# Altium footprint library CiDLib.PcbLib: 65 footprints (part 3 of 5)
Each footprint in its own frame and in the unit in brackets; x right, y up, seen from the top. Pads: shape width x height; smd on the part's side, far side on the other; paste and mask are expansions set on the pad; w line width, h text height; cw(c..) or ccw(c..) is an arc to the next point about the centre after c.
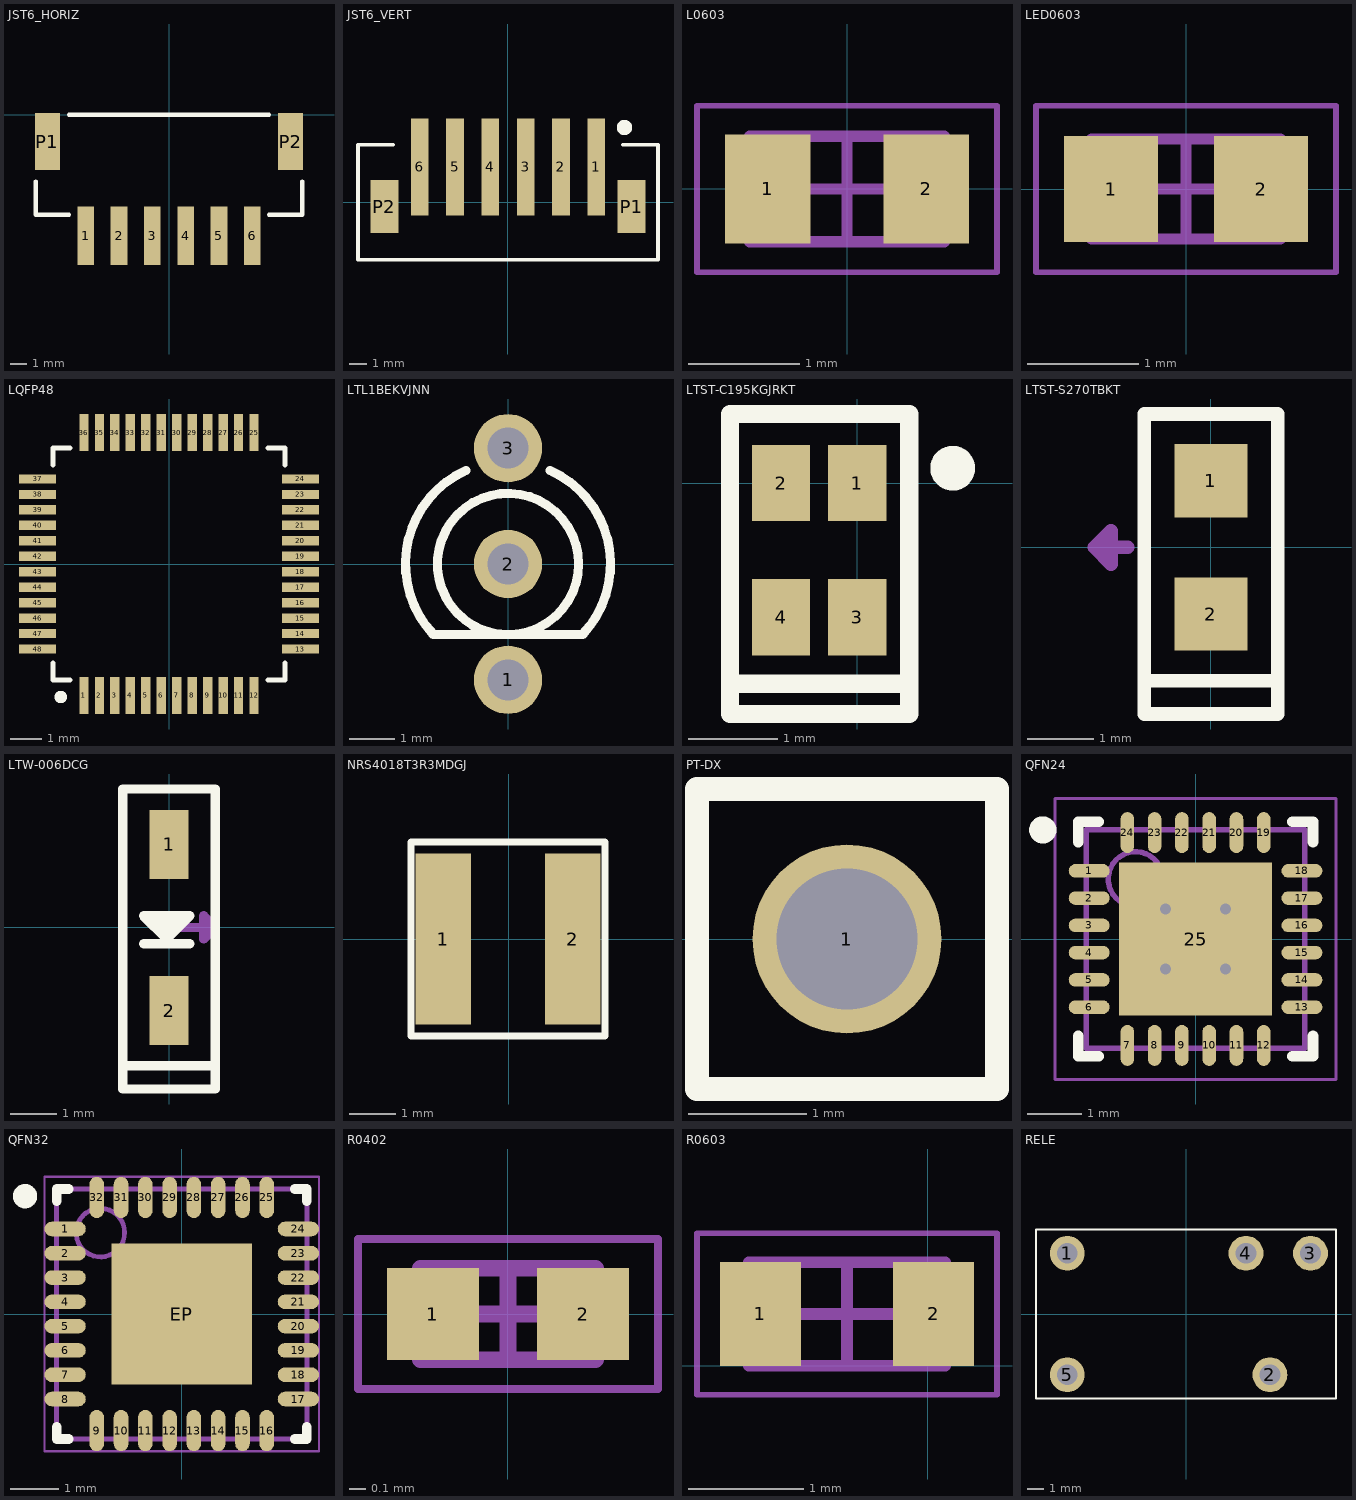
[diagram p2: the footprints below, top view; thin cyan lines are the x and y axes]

## JST6_HORIZ [mm] "SMT Horizontal JST 6 leads connector"
pads (8):
  rect 1x3.5 smd: 1(-5,-7.25) 2(-3,-7.25) 3(-1,-7.25) 4(1,-7.25) 5(3,-7.25) 6(5,-7.25)
  rect 1.5x3.4 smd: P1(-7.3,-1.6) P2(7.3,-1.6)
Top Overlay:
  lines w0.254: -8,-4 -8,-6 -6,-6 ; -6,0 6,0 ; 6,-6 8,-6 8,-4
3D body "S6B-PH-SM4-TB.STEP": height 5.5, standoff -0.1, extent -7.95,-8.6 7.95,0

## JST6_VERT [mm]
pads (8):
  rect 1x5.5 smd: 1(5,2) 2(3,2) 3(1,2) 4(-1,2) 5(-3,2) 6(-5,2)
  rect 1.6x3 smd: P1(7,-0.25) P2(-7,-0.25)
Top Overlay:
  circle w0.508: c6.605,4.235 r0.18
  lines w0.203: -6.5,3.25 -8.5,3.25 -8.5,-3.25 8.5,-3.25 8.5,3.25 6.5,3.25
3D body "A2001WV-S-6P.STEP": height 6.01, standoff 0.01, extent -8,-2.75 8,4.75

## L0603 [mm]
height 0.8
pads (2):
  rect 0.77x0.98 smd: 1(-0.715,0) 2(0.715,0)
Mechanical 13:
  lines w0.1: -0.875,-0.475 -0.875,0.475 0.875,0.475 0.875,-0.475 -0.875,-0.475
Mechanical 15:
  lines w0.05: -1.35,-0.75 -1.35,0.75 1.35,0.75 1.35,-0.75 -1.35,-0.75
  lines w0.1: -0.475,0 0.475,0 ; 0,-0.475 0,0.475
3D body: height 0.8, standoff 0, extent -0.575,-0.475 0.575,0.475
3D body: height 0.8, standoff 0, extent -0.875,-0.475 -0.575,0.475
3D body: height 0.8, standoff 0, extent 0.575,-0.475 0.875,0.475

## LED0603 [mm]
height 0.4
pads (2):
  rect 0.85x0.95 smd: 1(-0.675,0) 2(0.675,0)
Mechanical 13:
  lines w0.1: -0.85,-0.45 -0.85,0.45 0.85,0.45 0.85,-0.45 -0.85,-0.45
Mechanical 15:
  lines w0.05: -1.35,-0.75 -1.35,0.75 1.35,0.75 1.35,-0.75 -1.35,-0.75
  lines w0.1: -0.45,0 0.45,0 ; 0,-0.45 0,0.45
3D body: height 0.4, standoff 0, extent -0.45,-0.45 0.45,0.45
3D body: height 0.4, standoff 0, extent -0.85,-0.45 -0.45,0.45
3D body: height 0.4, standoff 0, extent 0.45,-0.45 0.85,0.45

## LQFP48 [mm]
pads (48):
  rect 0.3x1.2 smd mask+0.051: 1(-2.75,-4.25) 2(-2.25,-4.25) 3(-1.75,-4.25) 4(-1.25,-4.25) 5(-0.75,-4.25) 6(-0.25,-4.25) 7(0.25,-4.25) 8(0.75,-4.25) 9(1.25,-4.25) 10(1.75,-4.25) 11(2.25,-4.25) 12(2.75,-4.25) 25(2.75,4.25) 26(2.25,4.25) 27(1.75,4.25) 28(1.25,4.25) 29(0.75,4.25) 30(0.25,4.25) 31(-0.25,4.25) 32(-0.75,4.25) 33(-1.25,4.25) 34(-1.75,4.25) 35(-2.25,4.25) 36(-2.75,4.25)
  rect 1.2x0.3 smd mask+0.051: 13(4.25,-2.75) 14(4.25,-2.25) 15(4.25,-1.75) 16(4.25,-1.25) 17(4.25,-0.75) 18(4.25,-0.25) 19(4.25,0.25) 20(4.25,0.75) 21(4.25,1.25) 22(4.25,1.75) 23(4.25,2.25) 24(4.25,2.75) 37(-4.25,2.75) 38(-4.25,2.25) 39(-4.25,1.75) 40(-4.25,1.25) 41(-4.25,0.75) 42(-4.25,0.25) 43(-4.25,-0.25) 44(-4.25,-0.75) 45(-4.25,-1.25) 46(-4.25,-1.75) 47(-4.25,-2.25) 48(-4.25,-2.75)
Top Overlay:
  circle w0.203: c-3.5,-4.3 r0.1
  lines w0.152: -3.75,-3.2 -3.75,-3.75 -3.2,-3.75 ; -3.75,3.2 -3.75,3.75 -3.2,3.75 ; 3.2,-3.75 3.75,-3.75 3.75,-3.2 ; 3.2,3.75 3.75,3.75 3.75,3.2
3D body: height 1.6, standoff 0, extent -3.5,-3.5 3.5,3.5

## LTL1BEKVJNN [mm] "LED GRN/RED DIFF 3MM ROUND T/H"
height 5.15
pads (3):
  round 1.5 hole 0.9: 1(0,-2.54) 2(0,0) 3(0,2.54)
Top Overlay:
  circle w0.2: c0,0 r1.55
  lines w0.2: -1.64,-1.55 1.64,-1.55 ; -1.64,-1.541 cw(c0,0) -0.923,2.052 ; 0.923,2.052 cw(c0,0) 1.64,-1.541
3D body "User Library-3mmBiColorLED.step": height 7.51, standoff -2.53, extent -2.024,-2.794 2.024,2.794

## LTST-C195KGJRKT [mm] "Green-Red 571nm 631nm 2V-2V  0606"
pads (4):
  rect 0.65x0.85 smd: 1(0,0) 2(-0.85,0) 3(0,-1.499) 4(-0.85,-1.499)
Top Overlay:
  circle w0.25: c1.067,0.166 r0.125
  lines w0.203: -1.419,-2.579 0.581,-2.579 ; -1.419,-2.579 -1.419,-2.242 0.581,-2.242 0.581,-2.579 ; -1.419,-2.579 -1.419,0.772 0.581,0.772 0.581,-2.579

## LTST-S270TBKT [mm]
pads (2):
  rect 1.1x1.1 smd: 1(0,1) 2(0,-1)
Top Overlay:
  lines w0.203: -1,-2 1,-2 ; -1,-2 -1,2 1,2 1,-2 ; -1,-2 -1,-2.5 1,-2.5 1,-2
Mechanical 13:
  lines w0.203: -1.25,0 -1.75,0 ; -1.75,0 -1.5,-0.25 -1.5,0.25 -1.75,0
3D body: height 0.6, standoff 0, extent -0.81,-0.825 0.34,0.825

## LTW-006DCG [mm]
pads (2):
  rect 0.85x1.5 smd: 1(0,1.8) 2(0,-1.8)
Top Overlay:
  region: -0.05,-0.25 -0.55,0.25 0.45,0.25
  lines w0.203: -0.55,-0.35 0.45,-0.35 ; -1,-3 1,-3 ; -1,-3 -1,3 1,3 1,-3 ; -1,-3 -1,-3.5 1,-3.5 1,-3 ; -0.55,0.25 0.45,0.25 -0.05,-0.25 -0.55,0.25
Mechanical 13:
  lines w0.203: 0,0 1,0 ; 1,0 0.75,0.25 0.75,-0.25 1,0

## NRS4018T3R3MDGJ [mm]
pads (2):
  rect 1.2x3.7 smd mask+0.064: 1(-1.422,0.01) 2(1.378,0.01)
Top Overlay:
  lines w0.152: -2.122,-2.09 -2.122,2.11 2.078,2.11 2.078,-2.09 -2.122,-2.09
Mechanical 11:
  lines w0.102: -2.122,-2.09 2.078,-2.09 2.078,2.11 -2.122,2.11 -2.122,-2.09

## PT-DX [mil]
pads (1):
  round 63 hole 47: 1(175,0)
Top Overlay:
  lines w8: 125,-50 125,50 225,50 225,-50 125,-50

## QFN24 [mm]
height 0.65
pads (25):
  oval 0.75x0.25 smd: 1(-1.95,1.25) 2(-1.95,0.75) 3(-1.95,0.25) 4(-1.95,-0.25) 5(-1.95,-0.75) 6(-1.95,-1.25) 13(1.95,-1.25) 14(1.95,-0.75) 15(1.95,-0.25) 16(1.95,0.25) 17(1.95,0.75) 18(1.95,1.25)
  oval 0.25x0.75 smd: 7(-1.25,-1.95) 8(-0.75,-1.95) 9(-0.25,-1.95) 10(0.25,-1.95) 11(0.75,-1.95) 12(1.25,-1.95) 19(1.25,1.95) 20(0.75,1.95) 21(0.25,1.95) 22(-0.25,1.95) 23(-0.75,1.95) 24(-1.25,1.95)
  rect 2.8x2.8 smd: 25(0,0)
via -0.55,0.55 diameter 0.5 hole 0.2
via 0.55,0.55 diameter 0.5 hole 0.2
via -0.55,-0.55 diameter 0.5 hole 0.2
via 0.55,-0.55 diameter 0.5 hole 0.2
Top Overlay:
  circle w0.25: c-2.8,2 r0.125
  lines w0.2: -2.15,-1.775 -2.15,-2.15 -1.775,-2.15 ; -2.15,1.775 -2.15,2.15 -1.775,2.15 ; 1.775,-2.15 2.15,-2.15 2.15,-1.775 ; 1.775,2.15 2.15,2.15 2.15,1.775
Mechanical 13:
  circle w0.1: c-1.1,1.1 r0.5
  lines w0.1: -2,-2 -2,2 2,2 2,-2 -2,-2
Mechanical 15:
  lines w0.05: -2.575,-2.575 -2.575,2.575 2.575,2.575 2.575,-2.575 -2.575,-2.575
  lines w0.1: -0.5,0 0.5,0 ; 0,-0.5 0,0.5
3D body "User Library-QFN 24 4x4.step": height 0.9, standoff 0, extent -2.002,-2.002 2.002,2.002

## QFN32 [mm]
height 1
pads (33):
  oval 0.85x0.3 smd: 1(-2.4,1.75) 2(-2.4,1.25) 3(-2.4,0.75) 4(-2.4,0.25) 5(-2.4,-0.25) 6(-2.4,-0.75) 7(-2.4,-1.25) 8(-2.4,-1.75) 17(2.4,-1.75) 18(2.4,-1.25) 19(2.4,-0.75) 20(2.4,-0.25) 21(2.4,0.25) 22(2.4,0.75) 23(2.4,1.25) 24(2.4,1.75)
  oval 0.3x0.85 smd: 9(-1.75,-2.4) 10(-1.25,-2.4) 11(-0.75,-2.4) 12(-0.25,-2.4) 13(0.25,-2.4) 14(0.75,-2.4) 15(1.25,-2.4) 16(1.75,-2.4) 25(1.75,2.4) 26(1.25,2.4) 27(0.75,2.4) 28(0.25,2.4) 29(-0.25,2.4) 30(-0.75,2.4) 31(-1.25,2.4) 32(-1.75,2.4)
  rect 2.9x2.9 smd: EP(0,0)
Top Overlay:
  circle w0.25: c-3.225,2.425 r0.125
  lines w0.2: -2.575,-2.325 -2.575,-2.575 -2.325,-2.575 ; -2.575,2.325 -2.575,2.575 -2.325,2.575 ; 2.325,-2.575 2.575,-2.575 2.575,-2.325 ; 2.325,2.575 2.575,2.575 2.575,2.325
Mechanical 13:
  circle w0.1: c-1.675,1.675 r0.5
  lines w0.1: -2.575,-2.575 -2.575,2.575 2.575,2.575 2.575,-2.575 -2.575,-2.575
Mechanical 15:
  lines w0.05: -2.825,-2.825 -2.825,2.825 2.825,2.825 2.825,-2.825 -2.825,-2.825
  lines w0.1: -0.5,0 0.5,0 ; 0,-0.5 0,0.5
3D body: height 1, standoff 0.05, extent -2.575,-2.575 2.575,2.575

## R0402 [mm] "Chip Resistor, 2-Leads, Body 1,00x0,50mm, IPC Medium Density"
height 0.45
pads (2):
  rect 0.55x0.55 smd: 1(-0.45,0) 2(0.45,0)
Mechanical 13:
  lines w0.1: -0.525,-0.275 0.525,-0.275 0.525,0.275 -0.525,0.275 -0.525,-0.275
Mechanical 15:
  lines w0.05: -0.9,-0.45 0.9,-0.45 0.9,0.45 -0.9,0.45 -0.9,-0.45
  lines w0.1: -0.275,0 0.275,0 ; 0,-0.275 0,0.275
3D body: height 0.45, standoff 0, extent 0.325,-0.275 0.525,0.275
3D body: height 0.45, standoff 0, extent -0.525,-0.275 -0.325,0.275
3D body: height 0.45, standoff 0, extent -0.325,-0.275 0.325,0.275

## R0603 [mm] "Chip Resistor, 2-Leads, Body 1.60x0.80mm, IPC Medium Density"
height 0.45
pads (2):
  rect 0.7x0.9 smd: 1(-1.45,0.45) 2(0.05,0.45)
Mechanical 13:
  lines w0.1: -1.55,0 0.15,0 0.15,0.9 -1.55,0.9 -1.55,0
Mechanical 15:
  lines w0.05: -2,-0.25 0.6,-0.25 0.6,1.15 -2,1.15 -2,-0.25
  lines w0.1: -1.15,0.45 -0.25,0.45 ; -0.7,0 -0.7,0.9
3D body: height 0.45, standoff 0, extent -0.1,0 0.15,0.9
3D body: height 0.45, standoff 0, extent -1.55,0 -1.3,0.9
3D body: height 0.45, standoff 0, extent -1.3,0 -0.1,0.9

## RELE [mil]
pads (5):
  round 86 hole 51.18: 1(-292.91,150) 2(207.09,-150) 3(307.09,150) 4(148.03,150) 5(-292.91,-150)
Top Overlay:
  lines w5: -370.08,-208.66 370.08,-208.66 370.08,208.66 -370.08,208.66 -370.08,-208.66
3D body: height 602.36, standoff 0, extent -370.06,-208.64 370.06,208.64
